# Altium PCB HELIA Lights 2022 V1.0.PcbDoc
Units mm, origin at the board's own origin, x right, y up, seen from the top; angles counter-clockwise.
Board outline 200 x 105.13 mm, 2 copper layers (Top Layer, Bottom Layer); 70 components, 57 nets, 253 pads, 40 vias.
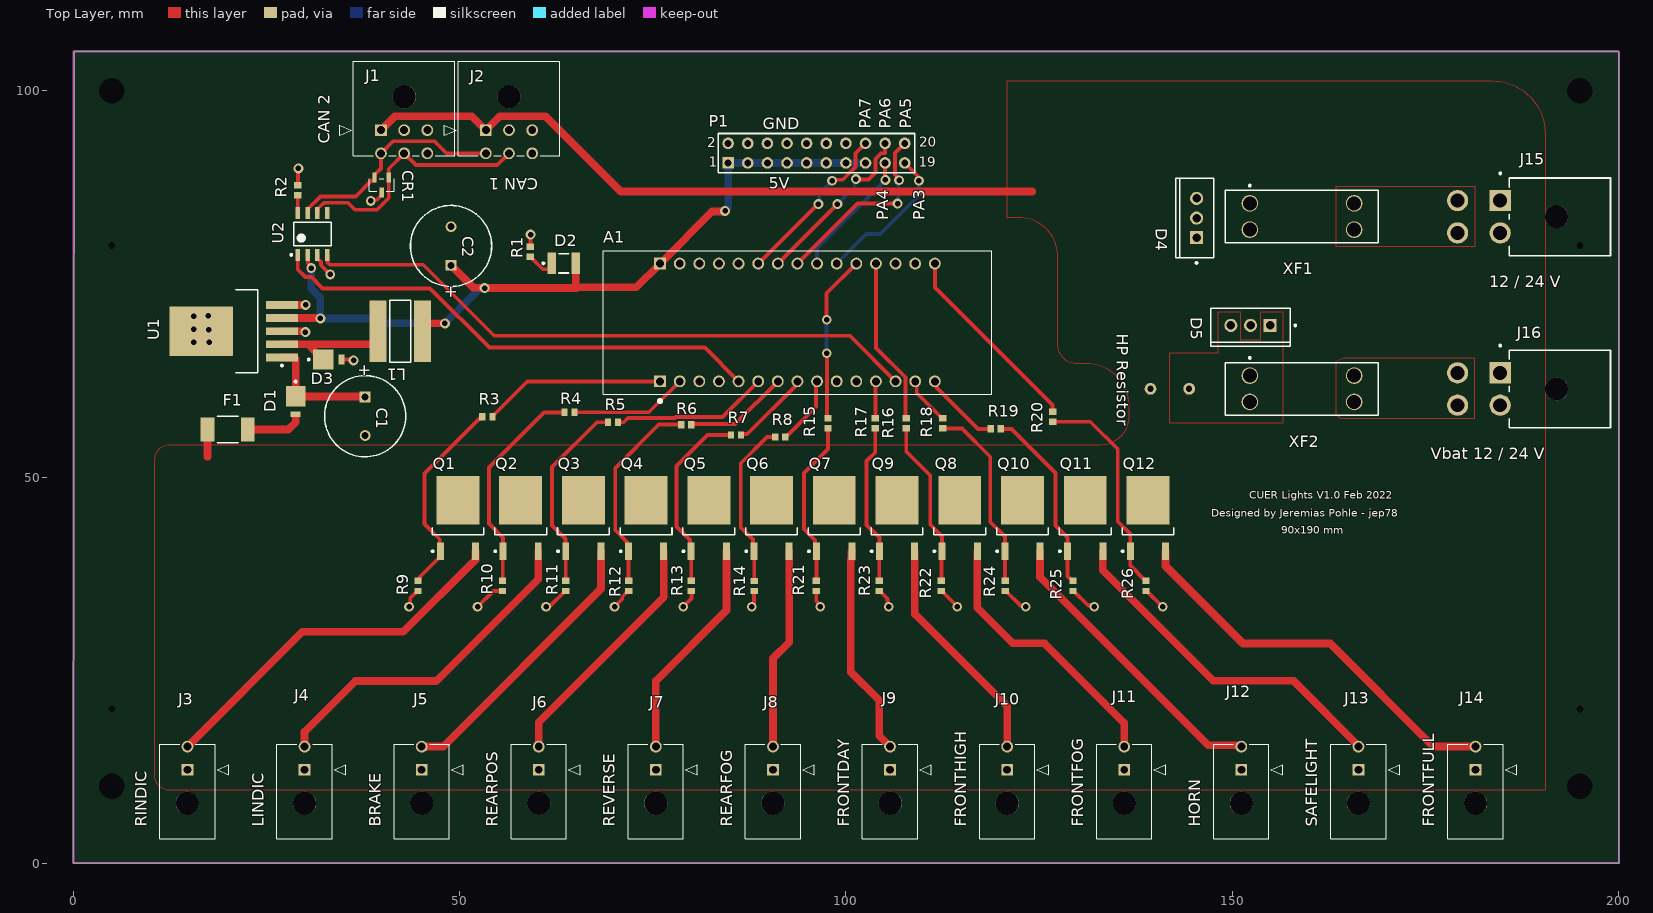
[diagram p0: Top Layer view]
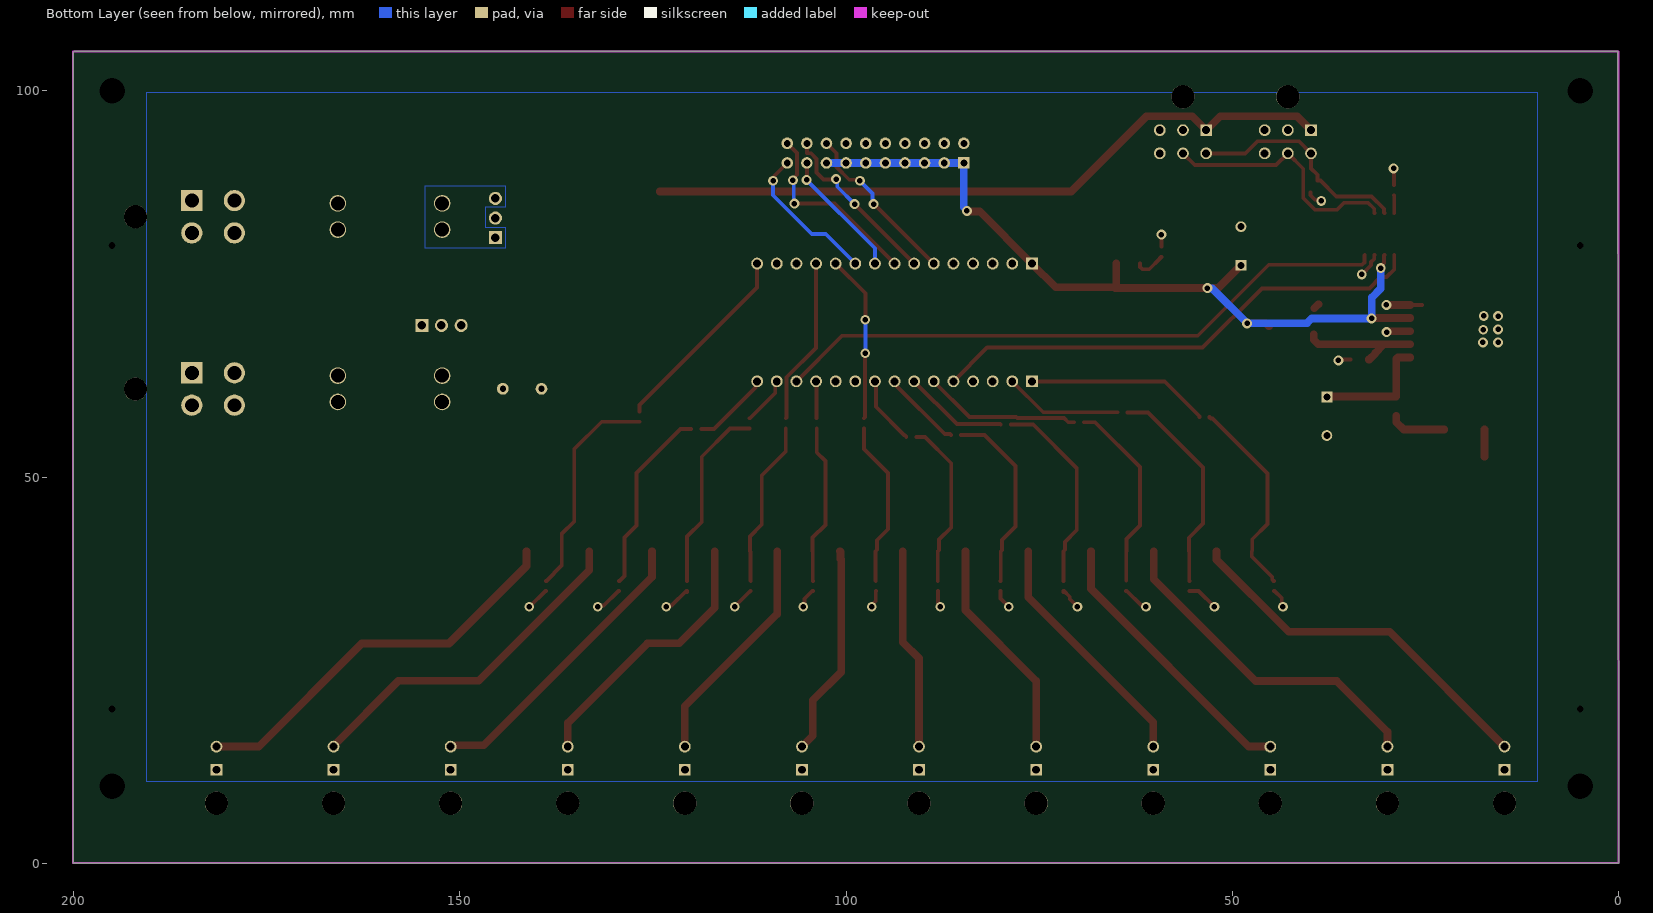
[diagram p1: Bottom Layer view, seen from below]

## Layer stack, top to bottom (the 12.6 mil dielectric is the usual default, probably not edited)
Top Solder: solder mask 0.0102, Solder Resist, Dk 3.5
Top Layer: signal copper 0.0356
Dielectric 1: dielectric 0.32, FR-4, Dk 4.6
Bottom Layer: signal copper 0.0356
Bottom Solder: solder mask 0.0102, Solder Resist, Dk 3.5

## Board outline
0,0 200,0 200,105 199.872,105.128 0.156,105.128

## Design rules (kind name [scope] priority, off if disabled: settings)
AssemblyTestPointUsage [All] p0: scope1count=1 scope1_0_kind=Board scope1_0_value=Board scope2count=1 scope2_0_kind=Board scope2_0_value=Board commentlength=0
AssemblyTestpoint [All] p0: scope1count=1 scope1_0_kind=Board scope1_0_value=Board scope2count=1 scope2_0_kind=Board scope2_0_value=Board commentlength=0
Clearance [All] p0: scope1count=1 scope1_0_kind=Board scope1_0_value=Board scope2count=1 scope2_0_kind=Board scope2_0_value=Board commentlength=0 gap=0.254
Clearance [All] p1: gap=0.254 ignorepadtopadclearanceinfootprint=TRUE except(0: Arc-Hole Track-Hole SMDPad-Hole THPad-Hole Via-Hole Fill-Hole Poly-Hole Region-Hole Text-Hole)
ComponentClearance [All] p0: scope1count=1 scope1_0_kind=Board scope1_0_value=Board scope2count=1 scope2_0_kind=Board scope2_0_value=Board commentlength=0 gap=0.254 collisioncheckmode=3
DiffPairsRouting [All] p0: scope1count=1 scope1_0_kind=Board scope1_0_value=Board scope2count=1 scope2_0_kind=Board scope2_0_value=Board commentlength=0
FabricationTestPointUsage [All] p0: scope1count=1 scope1_0_kind=Board scope1_0_value=Board scope2count=1 scope2_0_kind=Board scope2_0_value=Board commentlength=0 valid=2 allowmultiple=FALSE
FabricationTestPointUsage [All] p1: valid=2 allowmultiple=FALSE
FabricationTestpoint [All] p0: scope1count=1 scope1_0_kind=Board scope1_0_value=Board scope2count=1 scope2_0_kind=Board scope2_0_value=Board commentlength=0 side=3 testpointundercomponent=TRUE minsize=1.016 maxsize=2.54 preferedsize=1.524 minholesize=0 maxholesize=1.016 preferedholesize=0.813 testpointgrid=0.025
FanoutControl Fanout_BGA [All] p0 off: scope1count=1 scope1_0_kind=Board scope1_0_value=Board scope2count=1 scope2_0_kind=Board scope2_0_value=Board commentlength=69 // Protel DXP Scope 1 Expression Was: IsBGA   Fanout_BGA (Default Rule)
FanoutControl Fanout_LCC [All] p0 off: scope1count=1 scope1_0_kind=Board scope1_0_value=Board scope2count=1 scope2_0_kind=Board scope2_0_value=Board commentlength=69 // Protel DXP Scope 1 Expression Was: IsLCC   Fanout_LCC (Default Rule)
FanoutControl Fanout_SOIC [All] p0 off: scope1count=1 scope1_0_kind=Board scope1_0_value=Board scope2count=1 scope2_0_kind=Board scope2_0_value=Board commentlength=71 // Protel DXP Scope 1 Expression Was: IsSOIC   Fanout_SOIC (Default Rule)
FanoutControl Fanout_Small [All] p0 off: scope1count=1 scope1_0_kind=Board scope1_0_value=Board scope2count=1 scope2_0_kind=Board scope2_0_value=Board commentlength=84 // Protel DXP Scope 1 Expression Was: (CompPinCount < 5)   Fanout_Small (Default Rule)
FanoutControl Fanout_Default [All] p0: scope1count=1 scope1_0_kind=Board scope1_0_value=Board scope2count=1 scope2_0_kind=Board scope2_0_value=Board commentlength=30 // Fanout_Default (Default Rule)
Height [All] p0: scope1count=1 scope1_0_kind=Board scope1_0_value=Board scope2count=1 scope2_0_kind=Board scope2_0_value=Board commentlength=0
HoleSize [All] p0: scope1count=1 scope1_0_kind=Board scope1_0_value=Board scope2count=1 scope2_0_kind=Board scope2_0_value=Board commentlength=0 absolutevalues=TRUE maxlimit=6.3 minlimit=0.3 maxpercent=80.000 minpercent=20.000
HoleSize [All] p1: absolutevalues=TRUE maxlimit=6.3 minlimit=0.3 maxpercent=80.000 minpercent=20.000
HoleToHoleClearance [All] p0: scope1count=1 scope1_0_kind=Board scope1_0_value=Board scope2count=1 scope2_0_kind=Board scope2_0_value=Board commentlength=0
HoleToHoleClearance [All] p1: gap=0.5 allowstackedmicrovias=TRUE
LayerPairs [All] p0: scope1count=1 scope1_0_kind=Board scope1_0_value=Board scope2count=1 scope2_0_kind=Board scope2_0_value=Board commentlength=0 enforce=TRUE
MinimumSolderMaskSliver [All] p0: scope1count=1 scope1_0_kind=Board scope1_0_value=Board scope2count=1 scope2_0_kind=Board scope2_0_value=Board commentlength=0
MinimumSolderMaskSliver [All] p1: minsoldermaskwidth=0.1
NetAntennae [All] p0: scope1count=1 scope1_0_kind=Board scope1_0_value=Board scope2count=1 scope2_0_kind=Board scope2_0_value=Board commentlength=0
PasteMaskExpansion [All] p0: scope1count=1 scope1_0_kind=Board scope1_0_value=Board scope2count=1 scope2_0_kind=Board scope2_0_value=Board commentlength=0 expansion=0
PlaneClearance [All] p0: scope1count=1 scope1_0_kind=Board scope1_0_value=Board scope2count=1 scope2_0_kind=Board scope2_0_value=Board commentlength=0 clearance=0.508
PlaneConnect [All] p0: scope1count=1 scope1_0_kind=Board scope1_0_value=Board scope2count=1 scope2_0_kind=Board scope2_0_value=Board commentlength=0 planeconnectstyle=Relief reliefexpansion=0.508 reliefentries=4 reliefconductorwidth=0.254 reliefairgap=0.254
PolygonConnect [All] p0: scope1count=1 scope1_0_kind=Board scope1_0_value=Board scope2count=1 scope2_0_kind=Board scope2_0_value=Board commentlength=0 connectstyle=Direct reliefconductorwidth=0.508 reliefentries=4 polygonreliefangle="90 Angle"
PolygonConnect [All] p1: connectstyle=Direct reliefconductorwidth=0.508 reliefentries=4 polygonreliefangle="90 Angle" airgapwidth=0.254
RoutingCorners [All] p0: scope1count=1 scope1_0_kind=Board scope1_0_value=Board scope2count=1 scope2_0_kind=Board scope2_0_value=Board commentlength=0 cornerstyle=45-Degree minsetback=2.54 maxsetback=2.54
RoutingLayers [All] p0: scope1count=1 scope1_0_kind=Board scope1_0_value=Board scope2count=1 scope2_0_kind=Board scope2_0_value=Board commentlength=0 top layer=Automatic bottom layer=Automatic
RoutingPriority [All] p0: scope1count=1 scope1_0_kind=Board scope1_0_value=Board scope2count=1 scope2_0_kind=Board scope2_0_value=Board commentlength=0
RoutingTopology [All] p0: scope1count=1 scope1_0_kind=Board scope1_0_value=Board scope2count=1 scope2_0_kind=Board scope2_0_value=Board commentlength=0 topology=Shortest
RoutingVias [All] p0: scope1count=1 scope1_0_kind=Board scope1_0_value=Board scope2count=1 scope2_0_kind=Board scope2_0_value=Board commentlength=0 holewidth=0.711 width=1.27 viastyle="Through Hole" minholewidth=0.2 minwidth=0.4 maxholewidth=0.711 maxwidth=1.27
RoutingVias [All] p1: holewidth=0.711 width=1.27 viastyle="Through Hole" minholewidth=0.2 minwidth=0.4 maxholewidth=0.711 maxwidth=1.27
ShortCircuit [All] p0: scope1count=1 scope1_0_kind=Board scope1_0_value=Board scope2count=1 scope2_0_kind=Board scope2_0_value=Board commentlength=0 allowed=FALSE
SilkToBoardRegionClearance [All] p0: scope1count=1 scope1_0_kind=Board scope1_0_value=Board scope2count=1 scope2_0_kind=Board scope2_0_value=Board commentlength=0
SilkToSilkClearance [All] p0: scope1count=1 scope1_0_kind=Board scope1_0_value=Board scope2count=1 scope2_0_kind=Board scope2_0_value=Board commentlength=0
SilkToSolderMaskClearance [All] p0 off: scope1count=1 scope1_0_kind=Board scope1_0_value=Board scope2count=1 scope2_0_kind=Board scope2_0_value=Board commentlength=44 // Protel DXP Scope 1 Expression Was: IsPad
SilkToSolderMaskClearance [IsPad] p1: minsilkscreentomaskgap=0.15 clearancetoexposedcopper=TRUE
SolderMaskExpansion [All] p0: scope1count=1 scope1_0_kind=Board scope1_0_value=Board scope2count=1 scope2_0_kind=Board scope2_0_value=Board commentlength=0 expansion=0.05
SolderMaskExpansion [All] p1: expansion=0.05 istentingtop=FALSE
UnRoutedNet [All] p0: scope1count=1 scope1_0_kind=Board scope1_0_value=Board scope2count=1 scope2_0_kind=Board scope2_0_value=Board commentlength=0
UnpouredPolygon [All] p0: scope1count=1 scope1_0_kind=Board scope1_0_value=Board scope2count=1 scope2_0_kind=Board scope2_0_value=Board commentlength=0
Width [All] p0: scope1count=1 scope1_0_kind=Board scope1_0_value=Board scope2count=1 scope2_0_kind=Board scope2_0_value=Board commentlength=0 maxlimit=1 minlimit=0.175 preferedwidth=0.5
Width [All] p1: maxlimit=1 minlimit=0.175 preferedwidth=0.5
25 further rules are at their usual default settings.

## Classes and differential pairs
component class HELIALights2022V1.0Sheet2: D4 D5 J3 J4 J5 J6 J7 J8 J9 J10 J11 J12 J13 J14 J15 J16 P1 Q1 Q2 Q3 Q4 Q5 Q6 Q7 Q8 Q9 Q10 Q11 Q12 R3 R4 R5 R6 R7 R8 R9 R10 R11 R12 R13 R14 R15 R16 R17 R18 R19 R20 R21 R22 R23 R24 R25 R26 XF1 XF2
component class HELIALights2022V1.0Sheet1: A1 C1 C2 CR1 D1 D2 D3 F1 J1 J2 L1 R1 R2 U1 U2

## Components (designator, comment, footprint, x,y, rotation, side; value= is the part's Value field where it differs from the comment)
A1 "NUCLEO-F303K8" MODULE_NUCLEO-F303K8 93.743,70.013 r90 top
C1 "EEU-FR1C102B" PNSC-EEUFM1H221-2 37.795,57.878 r270 top
C2 "EEU-FR1C102B" PNSC-EEUFM1H221-2 48.912,79.908 r90 top
CR1 "DESD1CAN2SOQ-7" DIODE3_DESD1CAN2SOQ-7_DIO 39.93,87.802 r180 top
D1 "MBRM120LT3G" ONSC-POWERMITE-2-457-04_D_V 28.8,59.141 r270 top
D2 "LTST-C930KGKT" FP-LTST-C930KGKT-MFG 63.506,77.664 r0 top
D3 "MBRM120LT3G" ONSC-POWERMITE-2-457-04_D_V 33.715,65.214 r0 top
D4 "HTR20L120CT" ONSC-TO-220-3-221A-09 145.392,83.523 r180 top
D5 "HTR20L120CT" ONSC-TO-220-3-221A-09 152.374,69.623 r270 top
F1 "1812L035/30DR" FP-1812L035-30DR-MFG 19.998,56.162 r0 top
J1 "430450601" CON_430450601_MOL 39.842,94.898 r180 top
J2 "430450601" CON_430450601_MOL 53.413,94.898 r180 top
J3 "430450202" CON_430450202_MOL 14.8,12.12 r0 top
J4 "430450202" CON_430450202_MOL 29.955,12.12 r0 top
J5 "430450202" CON_430450202_MOL 45.109,12.12 r0 top
J6 "430450202" CON_430450202_MOL 60.264,12.12 r0 top
J7 "430450202" CON_430450202_MOL 75.418,12.12 r0 top
J8 "430450202" CON_430450202_MOL 90.573,12.12 r0 top
J9 "430450202" CON_430450202_MOL 105.727,12.12 r0 top
J10 "430450202" CON_430450202_MOL 136.036,12.12 r0 top
J11 "430450202" CON_430450202_MOL 120.882,12.12 r0 top
J12 "430450202" CON_430450202_MOL 151.191,12.12 r0 top
J13 "430450202" CON_430450202_MOL 166.345,12.12 r0 top
J14 "430450202" CON_430450202_MOL 181.5,12.12 r0 top
J15 "39-30-0040" FP-39-30-0040-MFG 192.233,83.69 r90 top
J16 "39-30-0040" FP-39-30-0040-MFG 192.233,61.398 r90 top
L1 "SRN8040-101M" BOUR-SRN8040-101M_V 42.338,68.881 r0 top
P1 "Header 10X2" HDR2X10 84.77,90.656 r0 top
Q1 "NCE3080K" INF-PG-TO252-3-313_L 49.8,44.7 r90 top
Q2 "NCE3080K" INF-PG-TO252-3-313_L 57.918,44.7 r90 top
Q3 "NCE3080K" INF-PG-TO252-3-313_L 66.036,44.7 r90 top
Q4 "NCE3080K" INF-PG-TO252-3-313_L 74.155,44.7 r90 top
Q5 "NCE3080K" INF-PG-TO252-3-313_L 82.273,44.7 r90 top
Q6 "NCE3080K" INF-PG-TO252-3-313_L 90.391,44.7 r90 top
Q7 "NCE3080K" INF-PG-TO252-3-313_L 98.509,44.7 r90 top
Q8 "NCE3080K" INF-PG-TO252-3-313_L 114.745,44.7 r90 top
Q9 "NCE3080K" INF-PG-TO252-3-313_L 106.627,44.7 r90 top
Q10 "NCE3080K" INF-PG-TO252-3-313_L 122.864,44.7 r90 top
Q11 "NCE3080K" INF-PG-TO252-3-313_L 130.982,44.7 r90 top
Q12 "NCE3080K" INF-PG-TO252-3-313_L 139.1,44.7 r90 top
R1 "2k7" RESC1609X50X30NL8T20 59.176,79.155 r270 top
R2 "10k" RESC1609X50X30NL8T20 29.084,87.123 r90 top
R3 "10k" RESC1609X50X30NL8T20 53.61,57.797 r0 top
R4 "10k" RESC1609X50X30NL8T20 64.243,58.373 r0 top
R5 "10k" RESC1609X50X30NL8T20 69.858,57.096 r0 top
R6 "10k" RESC1609X50X30NL8T20 79.348,56.782 r0 top
R7 "10k" RESC1609X50X30NL8T20 85.789,55.443 r0 top
R8 "10k" RESC1609X50X30NL8T20 91.507,55.181 r0 top
R9 "100k" RESC1609X50X30NL8T20 44.633,35.924 r270 top
R10 "100k" RESC1609X50X30NL8T20 55.576,35.924 r270 top
R11 "100k" RESC1609X50X30NL8T20 63.773,35.928 r270 top
R12 "100k" RESC1609X50X30NL8T20 71.892,35.924 r270 top
R13 "100k" RESC1609X50X30NL8T20 80.017,35.924 r270 top
R14 "100k" RESC1609X50X30NL8T20 88.138,35.893 r270 top
R15 "10k" RESC1609X50X30NL8T20 97.696,56.961 r90 top
R16 "10k" RESC1609X50X30NL8T20 107.823,56.961 r90 top
R17 "10k" RESC1609X50X30NL8T20 103.812,56.961 r90 top
R18 "10k" RESC1609X50X30NL8T20 112.525,56.961 r90 top
R19 "10k" RESC1609X50X30NL8T20 119.398,56.237 r180 top
R20 "10k" RESC1609X50X30NL8T20 126.763,57.816 r90 top
R21 "100k" RESC1609X50X30NL8T20 96.172,35.924 r270 top
R22 "100k" RESC1609X50X30NL8T20 112.346,35.924 r270 top
R23 "100k" RESC1609X50X30NL8T20 104.315,35.924 r270 top
R24 "100k" RESC1609X50X30NL8T20 120.618,35.924 r270 top
R25 "100k" RESC1609X50X30NL8T20 129.399,35.924 r270 top
R26 "100k" RESC1609X50X30NL8T20 138.857,35.924 r270 top
U1 "LM2576S-5.0" KTT0005B_N 20.768,68.881 r180 top
U2 "MCP2551-I/SN" MCHP-SN8_V 30.981,81.458 r90 top
XF1 "3557-2" KSTN-3557-2 159.034,83.723 r0 top
XF2 "3557-2" KSTN-3557-2 159.034,61.423 r0 top

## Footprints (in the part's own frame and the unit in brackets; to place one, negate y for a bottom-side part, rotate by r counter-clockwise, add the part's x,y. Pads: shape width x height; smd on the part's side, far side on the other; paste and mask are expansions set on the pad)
BOUR-SRN8040-101M_V [mm] "SMD, 2-Leads, Body 8x8mm"
  rect 2.2x8 smd: 1(-2.85,0) 2(2.85,0)
  silkscreen extent -1.35,-4 1.35,4
CON_430450202_MOL [mm]
  rect 1.52x1.52 hole 1.02 mask+0: 1(0,0)
  round 1.52 hole 1.02 mask+0: 2(0,3)
  round 3 hole 3 unplated mask+0: M1(0,-4.32)
  silkscreen extent -3.57,-8.92 5.35,3.32
CON_430450601_MOL [mm]
  rect 1.52x1.52 hole 1.02 mask+0: 1(0,0)
  round 1.52 hole 1.02 mask+0: 2(-3,0) 3(-6,0) 4(0,3) 5(-3,3) 6(-6,3)
  round 3 hole 3 unplated mask+0: M1(-3,-4.32)
  silkscreen extent -9.57,-8.92 5.35,3.32
DIODE3_DESD1CAN2SOQ-7_DIO [mil]
  rect 22x50 smd paste+0 mask+0: 1(-36.02,-38.21) 2(36.02,-38.21) 3(0,38.21)
  silkscreen extent -64,-33 64,33
FP-39-30-0040-MFG [mm]
  rect 2.75x2.75 hole 1.8 paste-1000 mask+0: 1(2.095,7.544)
  round 2.75 hole 1.8 paste-1000 mask+0: 2(-2.096,7.544) 3(2.095,13.056) 4(-2.096,13.056)
  round 2.997 hole 2.997 unplated paste-1000 mask+0: ""(0,0.254)
  silkscreen extent -5.02,-6.73 5.74,7.67
FP-1812L035-30DR-MFG [mm]
  rect 1.78x3.15 smd paste+0 mask+0: 1(-2.615,0) 2(2.615,0)
  silkscreen extent -1.35,-1.71 1.35,1.71
FP-LTST-C930KGKT-MFG [mm]
  rect 1.1x2.8 smd paste+0 mask+0: 1(-1.55,0) 2(1.55,0)
  silkscreen extent -2.77,-1.25 0.63,1.25
HDR2X10 [mm] "Connector; Header; 10x2 Position"
  rect 1.5x1.5 hole 0.9: 1(0,0)
  round 1.5 hole 0.9: 2(0,2.54) 3(2.54,0) 4(2.54,2.54) 5(5.08,0) 6(5.08,2.54) 7(7.62,0) 8(7.62,2.54) 9(10.16,0) 10(10.16,2.54) 11(12.7,0) 12(12.7,2.54) 13(15.24,0) 14(15.24,2.54) 15(17.78,0) 16(17.78,2.54) 17(20.32,0) 18(20.32,2.54) 19(22.86,0) 20(22.86,2.54)
  silkscreen extent -1.27,-1.27 24.13,3.81
INF-PG-TO252-3-313_L [mm] "DPAK, 3-Leads, Body 6.5x6.12mm, Pitch 2.28mm, IPC High Density"
  rect 2.25x0.9 smd: 1(-4.3,2.28) 3(-4.3,-2.28)
  rect 6.3x5.55 smd: 2(2.3,0)
  silkscreen extent -4.42,-3.35 -1.25,3.4
KSTN-3557-2 [mm] "Fuse Holder, PCB Mount, Thru-Hole, Body 19.8x6.8mm, Height 7.4mm"
  round 2.15 hole 1.8: 1(-6.75,1.7) 2(-6.75,-1.7) 3(6.75,1.7) 4(6.75,-1.7)
  silkscreen extent -9.9,-3.4 9.9,4.12
KTT0005B_N [mm] "DPAK, 5-Leads, Body 10.65x9.65mm, Pitch 1.7mm, IPC Medium Density"
  rrect10% 4.15x1 smd: 1(-6.25,3.4) 2(-6.25,1.7) 3(-6.25,0) 4(-6.25,-1.7) 5(-6.25,-3.4)
  rrect2% 8.2x6.4 smd: 6(4.2,0)
  silkscreen extent -6.38,-5.35 -0.3,5.35
MCHP-SN8_V [mm] "SOIC, 8-Leads, Body 4.9x3.9mm, Pitch 1.27mm"
  rect 1.55x0.6 smd: 1(-2.7,1.905) 2(-2.7,0.635) 3(-2.7,-0.635) 4(-2.7,-1.905) 5(2.7,-1.905) 6(2.7,-0.635) 7(2.7,0.635) 8(2.7,1.905)
  silkscreen extent -2.82,-2.45 1.53,2.88
MODULE_NUCLEO-F303K8 [mm]
  rect 1.53x1.53 hole 1.02: 3.1(-7.62,17.78) 4.1(7.62,17.78)
  round 1.53 hole 1.02: 3.2(-7.62,15.24) 3.3(-7.62,12.7) 3.4(-7.62,10.16) 3.5(-7.62,7.62) 3.6(-7.62,5.08) 3.7(-7.62,2.54) 3.8(-7.62,0) 3.9(-7.62,-2.54) 3.10(-7.62,-5.08) 3.11(-7.62,-7.62) 3.12(-7.62,-10.16) 3.13(-7.62,-12.7) 3.14(-7.62,-15.24) 3.15(-7.62,-17.78) 4.2(7.62,15.24) 4.3(7.62,12.7) 4.4(7.62,10.16) 4.5(7.62,7.62) 4.6(7.62,5.08) 4.7(7.62,2.54) 4.8(7.62,0) 4.9(7.62,-2.54) 4.10(7.62,-5.08) 4.11(7.62,-7.62) 4.12(7.62,-10.16) 4.13(7.62,-12.7) 4.14(7.62,-15.24) 4.15(7.62,-17.78)
  silkscreen extent -10.36,-25.14 9.27,25.14
ONSC-POWERMITE-2-457-04_D_V [mm] "POWERMITE, 2-Leads, Body 1.965x1.9mm"
  rect 2.67x2.54 smd: 1(-1.335,0)
  rect 0.762x1.27 smd: 2(1.016,0)
  silkscreen extent -3.34,-0.12 -3.1,0.13
ONSC-TO-220-3-221A-09 [mm] "FM, 3-Leads, Body 10.3x4.85mm, Pitch 2.54mm"
  rect 1.7x1.7 hole 1.1: 1(0,2.54)
  round 1.7 hole 1.1: 2(0,0) 3(0,-2.54)
  silkscreen extent -2.2,-5.15 2.7,5.92
PNSC-EEUFM1H221-2 [mm] "THD, 2-Leads, Dia 10.5mm, Body Length 17.5mm, Pin Spacing 5mm"
  rect 1.4x1.4 hole 0.9: 1(-2.5,0)
  round 1.4 hole 0.9: 2(2.5,0)
  silkscreen extent -5.25,-5.25 5.25,5.25
RESC1609X50X30NL8T20 [mm] "Chip Resistor, 2-Leads, Body 1.65x0.95mm, IPC Medium Density"
  rect 0.8x0.95 smd: 1(-0.65,0) 2(0.65,0)

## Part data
A1: "STM32F303K8, mbed-Enabled Development Nucleo-32 STM32F3 ARM® Cortex®-M4 MCU 32-Bit Embedded Evaluation Board"
C1 C2: library part CMP-2000-05313-1, "Aluminum Electrolytic Capacitor, 1000 uF, +/- 20%, 16 V, -40 to 105 degC, 2-Pin THD, RoHS, Tape and Reel"
CR1 J1 J2 J3 J4 J5 J6 J7 J8 J9 J10 J11 J12 J13 J14: "No Description Available"
D1 D3: library part CMP-1055-00263-1, "Schottky Power Rectifier, 2-Pin Powermite, Pb-Free, Tape and Reel"
D2: library part CMP-2000-06626-2, "LED GREEN CLEAR CHIP SMD"
D4 D5: library part CMP-1055-00618-1, "SWITCHMODE(TM) Power Rectifier, 60 V, 30 A, 3-Pin TO-220, Pb-Free, Tube"
F1: library part CMP-08606-000005-1, "PTC RESET FUSE 30V 350MA 1812"
J15 J16: library part CMP-2000-05600-2, "CONN HEADER R/A 4POS 4.2MM"
L1: library part CMP-2000-07143-1, "Semi-Shielded Power Inductor, 100 uH, -40 to 125 degC, 2-Pin SMD, RoHS, Tape and Reel"
P1: "Header, 10-Pin, Dual row"
Q1 Q2 Q3 Q4 Q5 Q6 Q7 Q8 Q9 Q10 Q11 Q12: library part CMP-1164-00349-1, "N-Channel CoolMOS E6 Power-Transistor, 600 V VDS, 7.3 A ID, -55 to 150 degC, PG-TO252-3-313, Reel, Green"
R1 R2 R3 R4 R5 R6 R7 R8 R9 R10 R11 R12 R13 R14 R15 R16 R17 R18 R19 R20 R21 R22 R23 R24 R25 R26: library part CMP-2000-03816-5, "Chip Resistor, 0 Ohm, Jumper, 100 mW, -55 to 155 degC, 0603 (1608 Metric), RoHS, Tape and Reel"
U1: library part CMP-0069-00115-3, "SIMPLE SWITCHER® 3A Step-Down Voltage Regulator, 5-pin TO-263"
U2: library part CMP-0186-00138-3, "High-Speed CAN Transceiver, /  1 Mb/s, 4.5 to 5.5 V, 8-Pin SOIC (SN), Industrial Temperature, RoHS, Tube"
XF1 XF2: library part CMP-2000-05461-1, "FUSE HOLDER, PCB MOUNT, 500VAC, 20A, ROHS"

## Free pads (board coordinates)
  round 1.524 hole 0.8: 10(139.434,61.423) 10(144.434,61.423)
  round 1.524 hole 3.3 unplated: 11(5,10) 12(5,100) 13(195,100) 14(195,10)
  round 0 hole 0.9 unplated: 15(5,20) 16(195,20) 17(195,80) 18(5,80)

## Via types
v1: diameter 1.27, hole 0.711, Top Layer to Bottom Layer, 40 vias

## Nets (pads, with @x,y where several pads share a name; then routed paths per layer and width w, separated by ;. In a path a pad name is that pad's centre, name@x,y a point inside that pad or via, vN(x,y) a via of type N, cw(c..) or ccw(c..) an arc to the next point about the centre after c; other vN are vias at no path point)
5V: A1.4.1 C2.1 D2.2 L1.2 P1.1 P1.3 P1.5 P1.7 P1.9 P1.11 P1.13 P1.15 U1.4 U2.2 | length 108.7
  Top Layer w0.5: U2.2 30.396,78.708 30.396,77.687 30.818,77.265 v1(30.818,77.056)
  Top Layer w1: U1.4 31.949,70.581 v1(31.998,70.532) ; L1.2@45.285,69.513 45.667,69.894 v1(48.113,69.894) ; C2.1 51.812,74.508 53.198,74.508 v1(53.25,74.457) 65.166,74.457 65.056,74.567 ; D2.2 65.056,74.567 ; v1@84.368,84.363 v1(84.368,84.436) 84.316,84.385 82.715,84.385 A1.4.1 72.897,74.567 65.056,74.567
  Bottom Layer w1: v1(30.818,77.056) 30.818,74.41 31.998,73.23 v1(31.998,70.532) 39.737,70.532 40.374,69.894 v1(48.113,69.894) 52.624,74.405 53.198,74.405 v1(53.25,74.457) ; v1(84.368,84.436) 84.368,84.51 84.77,84.912 P1.1 P1.3 P1.5 P1.7 P1.9 P1.11 P1.13 P1.15
"+12 / +24": D4.2 D5.2 F1.1 J1.1 J2.1 pad.10@139.434,61.423 Q1.2 Q2.2 Q3.2 Q4.2 Q5.2 Q6.2 Q7.2 Q8.2 Q9.2 Q10.2 Q11.2 Q12.2 | length 94.1
  Top Layer w1: 17.377,52.637 17.383,52.643 F1.1 ; J1.1 41.655,96.71 51.601,96.71 J2.1 55.219,96.704 61.139,96.704 70.889,86.954 124.121,86.954
BRAKECONN: J5.2 Q3.3 | length 36.5
  Top Layer w1: J5.2 47.887,15.12 68.316,35.55 Q3.3
CAN_RX: A1.3.13 U2.4 | length 80.9
  Top Layer w0.5: U2.4 32.936,78.708 32.936,77.766 33.228,77.473 45.315,77.473 54.495,68.293 100.542,68.293 A1.3.13
CAN_TX: A1.3.5 U2.1 | length 64.9
  Top Layer w0.5: U2.1 29.076,76.877 30.08,75.873 30.831,75.873 32.275,74.43 46.205,74.43 53.872,66.763 81.753,66.763 A1.3.5
CANH: CR1.2 J1.4 J2.4 U2.7 | length 29.4
  Top Layer w0.5: U2.7 30.396,84.208 30.396,84.726 31.999,86.329 36.572,86.329 38.63,88.388 38.986,88.388 39.015,88.417 CR1.2 39.015,89.128 39.842,89.956 J1.4 41.409,93.464 46.793,93.464 48.36,91.898 J2.4
CANL: CR1.1 J1.5 J2.5 U2.6 | length 32.5
  Top Layer w0.5: U2.6 31.666,84.208 31.666,84.726 32.446,85.506 35.559,85.506 36.464,84.601 39.327,84.601 40.845,86.119 40.845,89.9 J1.5 44.36,90.381 54.896,90.381 J2.5
FRONTDAYCONN: J9.2 Q7.3 | length 27.4
  Top Layer w1: Q7.3 100.739,40.35 100.739,39.411 100.656,39.328 100.656,24.777 104.339,21.094 104.339,16.508 J9.2
FRONTFORGCONN: J11.2 Q9.3 | length 30.3
  Top Layer w0.3: J11.2 J11.2@120.9,15.138
  Top Layer w1: Q9.3 108.907,32.293 120.882,20.318 J11.2
FRONTFULLCONN: J14.2 Q12.3 | length 51.7
  Top Layer w1: Q12.3 141.38,38.487 151.403,28.464 162.683,28.464 176.026,15.12 J14.2
FRONTHIGHCONN: J10.2 Q8.3 | length 35.6
  Top Layer w0.3: Q8.3@117,40.375 Q8.3
  Top Layer w1: Q8.3 117.025,33.093 121.618,28.5 125.7,28.5 136.036,18.164 J10.2
GND: A1.3.4 A1.4.2 C1.2 C2.2 CR1.3 D3.2 J1.2 J2.2 J3.1 J4.1 J5.1 J6.1 J7.1 J8.1 J9.1 J10.1 J11.1 J12.1 J13.1 J14.1 J15.1 J15.2 J16.1 J16.2 P1.2 P1.4 P1.6 P1.8 P1.10 P1.12 P1.14 R1.1 R2.2 R9.2 R10.2 R11.2 R12.2 R13.2 R14.2 R21.2 R22.2 R23.2 R24.2 R25.2 R26.2 U1.3 U1.5 U1.6 U2.3 | length 54.6
  Top Layer w0.5: U1.5@25.443,72.281 U1.5 ; R2.2 29.119,87.808 29.119,89.909 v1(29.154,89.944) ; U2.3 31.666,78.708 31.666,78.233 32.082,77.817 32.082,77.416 v1(33.267,76.23) ; D3.2 36.168,65.214 v1(36.288,65.094) ; v1(38.53,85.74) 38.678,85.888 39.342,85.888 39.93,86.476 CR1.3 ; v1(43.479,33.219) 43.626,33.367 43.626,34.342 44.558,35.274 R9.2 ; v1(52.347,33.219) 54.402,35.274 R10.2 ; v1(59.199,81.383) 59.176,81.36 R1.1 R1.1@59.202,79.831 ; v1(61.215,33.219) 61.362,33.367 61.787,33.367 63.698,35.278 R11.2 ; v1(70.082,33.219) 71.062,34.199 71.062,34.519 71.817,35.274 R12.2 71.892,35.146 R12.2@71.913,35.124 ; v1(78.95,33.219) 80.017,34.286 R13.2 R13.2@80.004,35.262 ; v1(87.818,33.219) 87.818,33.428 88.138,33.747 R14.2 ; R14.2@88.14,35.214 R14.2@88.154,35.227 ; R21.2@96.148,35.25 R21.2 96.172,33.941 96.686,33.428 v1(96.686,33.219) ; R23.2@104.369,35.22 R23.2 104.39,35.274 105.407,34.257 105.407,33.367 v1(105.554,33.219) ; R22.2@112.414,35.207 R22.2 112.421,35.274 114.422,33.273 v1(114.422,33.219) ; R24.2@120.615,35.124 120.618,35.127 R24.2 120.693,35.274 122.601,33.367 123.143,33.367 v1(123.29,33.219) ; R25.2 129.474,35.274 131.382,33.367 132.011,33.367 v1(132.158,33.219) ; R26.2 138.932,35.274 140.987,33.219 v1(141.026,33.219)
  Top Layer w1: U1.3 29.865,68.881 29.987,68.759 v1(30.06,68.759) ; U1.5 30.077,72.281 v1(30.083,72.287)
  other v1: 15.643,67.427 17.59,67.427 17.55,69.063 15.643,69.105 15.626,70.834 17.499,70.86
HORNCONN: J12.2 Q10.3 | length 38.5
  Top Layer w1: Q10.3 125.144,37.056 146.907,15.293 150.651,15.293 150.724,15.219 151.091,15.219 J12.2
LINDICCONN: J4.2 Q2.3 | length 43.9
  Top Layer w1: J4.2 29.955,17.027 36.527,23.6 47.001,23.6 60.198,36.797 Q2.3
NetC1_1: C1.1 D1.1 U1.1 | length 15.7
  Top Layer w0.5: D1.1@28.791,61.6 D1.1@28.8,61.591
  Top Layer w1: U1.1 28.593,65.481 28.8,65.274 28.8,61.591 D1.1 28.849,60.427 37.746,60.427 C1.1
NetD1_2: D1.2 F1.2 | length 7.4
  Top Layer w1: F1.2 27.858,56.162 28.8,57.104 D1.2@28.8,57.905
NetD2_1: D2.1 R1.2 | length 4.1
  Top Layer w0.5: R1.2 59.251,78.505 59.401,78.355 59.401,78.28 60.779,76.901 61.656,76.901 61.956,77.201 D2.1
NetD3_1: D3.1 L1.1 U1.2 | length 17
  Top Layer w1: U1.2 30.413,67.181 ; D3.1 32.315,65.214 31.545,65.984 31.545,66.049 30.413,67.181 ; L1.1@38.888,72.38 39.42,71.847 L1.1@39.42,71.846 ; L1.1@39.488,68.456 39.488,67.781 38.888,67.181 30.413,67.181
NetD4_1: D4.1 D4.3 XF1.1 XF1.2 | length 0.3
  Top Layer w0.5: D4.3 D4.3@145.716,86.063
NetD5_1: D5.1 D5.3 pad.10@144.434,61.423 XF2.1 XF2.2
NetJ15_3: J15.3 J15.4 XF1.3 XF1.4 | length 0.2
  Top Layer w0.5: XF1.3@165.742,85.173 XF1.3@165.742,85.423
NetJ16_3: J16.3 J16.4 XF2.3 XF2.4 | length 0.9
  Top Layer w0.5: XF2.4 XF2.4@166.231,59.723 ; XF2.3 XF2.3@166.231,63.123
NetQ1_1: Q1.1 R3.1 R9.1 | length 26.5
  Top Layer w0.5: R9.1 44.708,36.574 44.858,36.724 44.858,37.063 47.52,39.725 Q1.1 47.443,40.477 47.443,41.958 45.485,43.916 45.485,50.476 52.581,57.572 52.81,57.572 52.96,57.722 R3.1
NetQ2_1: Q2.1 R4.1 R10.1 | length 28.2
  Top Layer w0.5: R10.1 55.607,36.605 55.607,40.369 Q2.1 55.638,42.142 53.803,43.977 53.803,51.233 60.943,58.373 R4.1
NetQ3_1: Q3.1 R5.1 R11.1 | length 25
  Top Layer w0.5: R11.1@63.756,36.594 Q3.1 63.737,40.419 63.737,41.982 61.995,43.724 61.995,51.29 67.801,57.096 R5.1
NetQ4_1: Q4.1 R6.1 R12.1 | length 26.2
  Top Layer w0.5: R12.1 71.883,36.583 71.883,40.391 Q4.1 71.675,40.6 71.675,41.619 70.17,43.124 70.17,51.162 75.79,56.782 R6.1
NetQ5_1: Q5.1 R7.1 R13.1 | length 24.4
  Top Layer w0.5: R13.1 80.005,36.586 80.005,40.388 Q5.1 79.824,40.568 79.824,41.867 78.11,43.581 78.11,51.456 82.097,55.443 R7.1
NetQ6_1: Q6.1 R8.1 R14.1 | length 21.9
  Top Layer w0.5: R14.1@88.159,36.574 88.159,40.352 Q6.1 87.984,40.527 87.984,41.909 86.41,43.483 86.41,51.79 89.802,55.181 R8.1 R8.1@90.923,55.181
NetQ7_1: Q7.1 R15.1 R21.1 | length 21.7
  Top Layer w0.5: R21.1 96.201,36.603 96.201,40.372 Q7.1 96.029,40.6 96.029,41.832 94.611,43.25 94.611,50.547 97.696,53.632 R15.1
NetQ8_1: Q8.1 R16.1 R22.1 | length 21.7
  Top Layer w0.5: R16.1 107.823,53.308 110.926,50.206 110.926,43.868 112.465,42.328 Q8.1 112.406,40.34 112.406,36.634 R22.1
NetQ9_1: Q9.1 R17.1 R23.1 | length 20.9
  Top Layer w0.5: R17.1 103.812,53.205 102.7,52.094 102.7,43.811 104.347,42.164 Q9.1 104.331,40.384 104.331,36.591 R23.1
NetQ10_1: Q10.1 R18.1 R24.1 | length 24.5
  Top Layer w0.5: R18.1 115.019,56.311 118.701,52.629 118.701,44.177 120.584,42.295 Q10.1 120.601,40.383 120.601,36.591 R24.1
NetQ11_1: Q11.1 R19.1 R25.1 | length 24.4
  Top Layer w0.5: R19.1 121.431,56.237 127.152,50.516 127.152,43.755 128.702,42.205 Q11.1 128.702,37.196 129.324,36.574 R25.1
NetQ12_1: Q12.1 R20.1 R26.1 | length 28.5
  Top Layer w0.5: R20.1 131.639,57.166 135.19,53.614 135.19,44.272 136.82,42.642 Q12.1 136.82,38.536 138.782,36.574 R26.1
NetR2_1: R2.1 U2.8 | length 2.3
  Top Layer w0.5: U2.8 29.08,84.162 29.08,86.469 R2.1
PA3: A1.4.10 P1.19 | length 19.2
  Top Layer w0.5: P1.19 109.315,88.971 109.315,88.49 v1(109.462,88.343)
  Bottom Layer w0.5: A1.4.10 102.652,81.461 104.457,81.461 109.462,86.467 v1(109.462,88.343)
PA4: A1.4.9 P1.17 | length 16.7
  Top Layer w0.5: P1.17 105.09,88.503 v1(105.127,88.467)
  Bottom Layer w0.5: A1.4.9 96.283,79.622 v1(105.127,88.467)
PA5: A1.4.8 P1.20 | length 24.8
  Top Layer w0.5: A1.4.8 101.498,85.388 v1(106.698,85.388) ; v1(106.886,88.404) 106.886,88.612 106.376,89.122 106.376,91.942 P1.20
  Bottom Layer w0.5: v1(106.698,85.388) 106.792,85.482 106.792,88.309 v1(106.886,88.404)
PA6: A1.4.7 P1.18 | length 22.7
  Top Layer w0.5: A1.4.7 91.209,77.633 98.901,85.325 v1(98.907,85.325) ; v1(101.299,88.56) 101.359,88.501 102.934,88.501 103.836,89.403 103.836,91.175 104.571,91.91 105.09,91.91 P1.18
  Bottom Layer w0.5: v1(98.907,85.325) 101.152,87.57 101.152,88.413 v1(101.299,88.56)
PA7: A1.4.6 P1.16 | length 22.1
  Top Layer w0.5: A1.4.6 88.714,77.633 96.406,85.325 v1(96.457,85.325) ; v1(98.216,88.343) 98.346,88.473 99.601,88.473 101.264,90.136 101.264,91.91 P1.16
  Bottom Layer w0.5: v1(96.457,85.325) 96.584,85.452 96.584,86.71 v1(98.216,88.343)
PINBRAKE: A1.3.6 R5.2 | length 20.3
  Top Layer w0.5: R5.2 71.268,57.096 71.807,57.635 77.856,57.635 78.006,57.785 84.055,57.785 A1.3.6
PINFRONTDAY: A1.4.11 R15.2 | length 21.7
  Top Layer w0.5: v1(97.523,66.031) 97.554,66 97.554,57.752 R15.2 ; v1(97.523,70.356) 97.523,73.793 A1.4.11
  Bottom Layer w0.5: v1(97.523,66.031) v1(97.523,70.356)
PINFRONTFOG: A1.3.12 R17.2 | length 4.8
  Top Layer w0.5: R17.2 103.857,57.656 103.857,62.347 A1.3.12
PINFRONTFULL: A1.4.15 R20.2 | length 25.5
  Top Layer w0.5: A1.4.15 111.523,74.54 126.74,59.323 126.74,58.489 R20.2
PINFRONTHIGH: A1.4.12 R16.2 | length 21.6
  Top Layer w0.5: A1.4.12 103.903,66.727 107.714,62.916 107.714,57.72 R16.2
PINHORN: A1.3.14 R18.2 | length 6.3
  Top Layer w0.5: A1.3.14 109.18,62.196 109.18,60.881 112.45,57.611 R18.2
PINLINDIC: A1.3.2 R4.2 | length 15.3
  Top Layer w0.5: R4.2@64.893,58.389 74.499,58.389 A1.3.2
PINREARFOG: A1.3.9 R8.2 | length 8.9
  Top Layer w0.5: R8.2@92.223,55.181 92.223,55.256 92.373,55.406 92.448,55.406 96.141,59.1 96.141,62.251 A1.3.9
PINREARPOS: A1.3.7 R6.2 | length 13.5
  Top Layer w0.5: R6.2 80.073,56.857 85.668,56.857 A1.3.7
PINREVERSE: A1.3.8 R7.2 | length 10.4
  Top Layer w0.5: R7.2 86.567,55.57 87.247,55.57 93.546,61.869 93.546,62.196 A1.3.8
PINRINDIC: A1.3.1 R3.2 | length 23.7
  Top Layer w0.5: R3.2 54.26,57.872 58.781,62.393 A1.3.1
PINSAFELIGHT: A1.3.15 R19.2 | length 10.1
  Top Layer w0.5: A1.3.15 111.72,62.196 111.72,61.613 117.096,56.237 R19.2
REARFOGCONN: J8.2 Q6.3 | length 26.1
  Top Layer w1: J8.2 90.573,26.551 92.671,28.65 Q6.3
REARPOSCONN: J6.2 Q4.3 | length 32
  Top Layer w1: J6.2 60.264,18.264 76.435,34.435 Q4.3
REVERSECONN: J7.2 Q5.3 | length 29.1
  Top Layer w1: J7.2 75.4,15.138 75.4,23.6 84.553,32.753 Q5.3
RINDICCONN: J3.2 Q1.3 | length 48.4
  Top Layer w1: J3.2 29.66,29.98 42.74,29.98 52.08,39.319 Q1.3
SAFELIGHTCONN: J13.2 Q11.3 | length 45
  Top Layer w1: Q11.3 133.262,37.938 147.565,23.635 157.939,23.635 J13.2@166.4,15.175
pads on no net: A1.3.3 A1.3.10 A1.3.11 A1.4.3 A1.4.4 A1.4.5 A1.4.13 A1.4.14 J1.3 J1.6 J1.M1 J2.3 J2.6 J2.M1 J3.M1 J4.M1 J5.M1 J6.M1 J7.M1 J8.M1 J9.M1 J10.M1 J11.M1 J12.M1 J13.M1 J14.M1 J15. J16. U2.5

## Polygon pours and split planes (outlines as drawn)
"+12 / +24" on Top Layer "+12_/_+24_L01_P029" (solid, pour order 29): 122.443,83.576 120.902,83.576 120.902,101.265 183.698,101.265 cw(c183.698,94.462) 190.5,94.462 190.5,9.5 12.121,9.5 cw(c12.511,11.417) 10.594,11.807 10.594,52.301 cw(c12.497,52.301) 12.497,54.204 132.975,54.204 ccw(c132.976,57.926) 136.697,57.926 136.697,59.117 ccw(c131.151,59.117) 131.151,64.664 129.96,64.664 cw(c129.96,67.204) 127.42,67.204 127.42,78.599 ccw(c122.443,78.6)
NetJ15_3 on Top Layer "NETJ15_3_L01_P026" (solid, remove dead copper, pour order 26): 181.381,87.623 181.381,79.791 163.492,79.791 163.492,81 163.492,86.523 163.492,87.623 168.617,87.623 170.115,87.623
NetJ16_3 on Top Layer "NETJ16_3_L01_P027" (solid, pour order 27): 181.351,57.523 169.999,57.523 164.127,57.523 163.484,58.023 163.484,65.023 164.384,65.423 181.351,65.423
NetD5_1 on Top Layer "NETD5_1_L01_P028" (solid, pour order 28): 156.634,71.323 153.634,71.323 153.634,67.723 151.134,67.723 151.134,71.323 148.134,71.323 148.134,66.023 141.834,66.023 141.834,57.023 156.634,57.023
GND on Bottom Layer "GND_L02_P031" (solid, pour order 31): 10.596,99.789 10.596,10.6 190.504,10.6 190.504,99.789
NetD4_1 on Bottom Layer "NETD4_1_L02_P030" (solid, pour order 30): 154.492,87.723 144.092,87.723 144.092,84.923 146.692,84.923 146.692,82.323 144.092,82.323 144.092,79.623 146.992,79.623 154.492,79.623

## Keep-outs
Keep-Out Layer:
  lines w0.254: 0.05,0.05 200.05,0.05 200.05,105.05 0.05,105.05 0.05,0.05

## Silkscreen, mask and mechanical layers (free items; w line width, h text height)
Top Overlay:
  text "PA7" at 103.243,95.076 h1.52 r90
  text "PA6" at 105.846,95.076 h1.52 r90
  text "PA5" at 108.448,95.076 h1.52 r90
  text "GND" at 89.23,95.026 h1.52
  text "CAN 2" at 33.231,93.128 h1.52 r90
  text "CAN 1" at 60.201,88.684 h1.52 r180
  text "5V" at 90.032,87.329 h1.52
  text "PA4" at 105.501,83.249 h1.52 r90
  text "PA3" at 110.241,83.249 h1.52 r90
  text "12 / 24 V" at 183.257,74.562 h1.52
  text "HP Resistor" at 135.088,68.569 h1.52 r270
  text "Vbat 12 / 24 V" at 175.734,52.285 h1.52
  text "CUER Lights V1.0 Feb 2022" at 152.229,47.188 h1
  text "Designed by Jeremias Pohle - jep78" at 147.304,44.881 h1
  text "90x190 mm" at 156.345,42.685 h1
  text "RINDIC" at 9.546,4.754 h1.52 r90
  text "LINDIC" at 24.691,4.754 h1.52 r90
  text "BRAKE" at 39.837,4.754 h1.52 r90
  text "REARPOS" at 54.982,4.754 h1.52 r90
  text "REVERSE" at 70.128,4.754 h1.52 r90
  text "REARFOG" at 85.273,4.754 h1.52 r90
  text "FRONTDAY" at 100.419,4.754 h1.52 r90
  text "FRONTHIGH" at 115.564,4.754 h1.52 r90
  text "FRONTFOG" at 130.71,4.754 h1.52 r90
  text "HORN" at 145.855,4.754 h1.52 r90
  text "SAFELIGHT" at 161.001,4.754 h1.52 r90
  text "FRONTFULL" at 176.146,4.754 h1.52 r90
